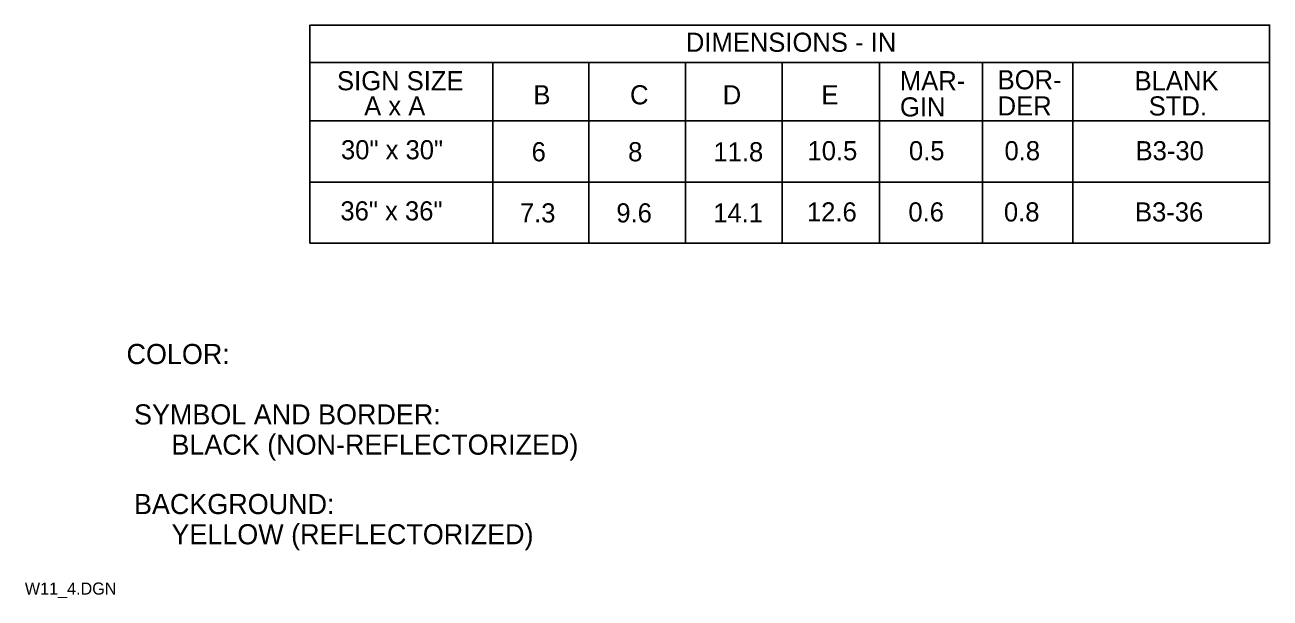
# Model space of a CAD drawing. Extents: x 0.01 to 2.78, y -0.74 to 0.6.
# Drawn here: x 0.013 to 0.1675, y 0.004 to 0.0751 of the extents above; entities that cross this region are included whole.
import ezdxf

# ---------------------------------------------------------------- set-up
doc = ezdxf.new("R2010")
doc.units = 0
doc.layers.add('1', color=7, linetype='Continuous')
doc.layers.add('3', color=7, linetype='Continuous')

msp = doc.modelspace()

# ---------------------------------------------------------------- linework, layer by layer
at = {"layer": '1'}
for p, q in [((0.16745, 0.07514), (0.16745, 0.04802)), ((0.13184, 0.07048), (0.13184, 0.04802)), ((0.14302, 0.07048), (0.14302, 0.04802))]:
    msp.add_line(p, q, dxfattribs=at)
at = {"layer": '3'}
for p, q in [((0.04832, 0.07514), (0.04832, 0.04802)), ((0.04839, 0.07511), (0.16752, 0.07511)), ((0.16752, 0.07048), (0.04839, 0.07048)), ((0.07102, 0.07048), (0.07102, 0.04802)), ((0.04839, 0.06323), (0.16752, 0.06323)), ((0.04839, 0.05561), (0.16752, 0.05561)), ((0.04832, 0.04802), (0.16745, 0.04802))]:
    msp.add_line(p, q, dxfattribs=at)
for points in [[(0.08295, 0.07052), (0.08295, 0.04802)], [(0.09495, 0.07052), (0.09495, 0.04802)], [(0.10695, 0.07052), (0.10695, 0.04802)], [(0.11902, 0.07048), (0.11902, 0.04802)]]:
    msp.add_lwpolyline(points, dxfattribs=at)

# ---------------------------------------------------------------- texts
at = {"layer": '1'}
for s, height, p in [('COLOR:', 0.0025, (0.02557, 0.03302)), (' SYMBOL AND BORDER:', 0.0024998, (0.02557, 0.02552)), ('      BLACK (NON-REFLECTORIZED)', 0.0024998, (0.02557, 0.02177)), (' BACKGROUND:', 0.0024998, (0.02557, 0.01439)), ('      YELLOW (REFLECTORIZED)', 0.0024998, (0.02557, 0.01064)), ('W11_4.DGN', 0.0015, (0.01295, 0.00439))]:
    msp.add_text(s, height=height, dxfattribs=at).set_placement(p)
at = {"layer": '3'}
for s, height, p in [('DIMENSIONS - IN', 0.0023752, (0.095, 0.0718)), ('SIGN SIZE', 0.002375, (0.0517, 0.06702)), ('MAR-', 0.002375, (0.12157, 0.06702)), ('BOR-', 0.002375, (0.1337, 0.06714)), ('BLANK', 0.002375, (0.1507, 0.06702)), ('B', 0.00238, (0.07607, 0.06527)), ('C', 0.00238, (0.08807, 0.06527)), ('D', 0.00238, (0.09957, 0.06527)), ('E', 0.00238, (0.11182, 0.06527)), ('A x A', 0.002375, (0.05507, 0.06389)), ('GIN', 0.002375, (0.12157, 0.06377)), ('DER', 0.002375, (0.1337, 0.06389)), ('STD.', 0.002375, (0.15245, 0.06389)), ('30" x 30"', 0.002375, (0.05219, 0.05845)), ('6', 0.00238, (0.07585, 0.0582)), ('8', 0.00238, (0.08783, 0.0582)), ('11.8', 0.002375, (0.09842, 0.0582)), ('10.5', 0.002375, (0.1101, 0.05833)), ('0.5', 0.002375, (0.12269, 0.05833)), ('0.8', 0.002375, (0.13455, 0.05833)), ('B3-30', 0.002375, (0.15082, 0.05833)), ('36" x 36"', 0.002375, (0.05212, 0.05086)), ('7.3', 0.002375, (0.0744, 0.05061)), ('9.6', 0.002375, (0.08637, 0.05061)), ('14.1', 0.002375, (0.0984, 0.05061)), ('12.6', 0.002375, (0.11003, 0.05073)), ('0.6', 0.002375, (0.12262, 0.05073)), ('0.8', 0.002375, (0.13448, 0.05073)), ('B3-36', 0.002375, (0.15075, 0.05073))]:
    msp.add_text(s, height=height, dxfattribs=at).set_placement(p)

doc.saveas('drawing.dxf')
